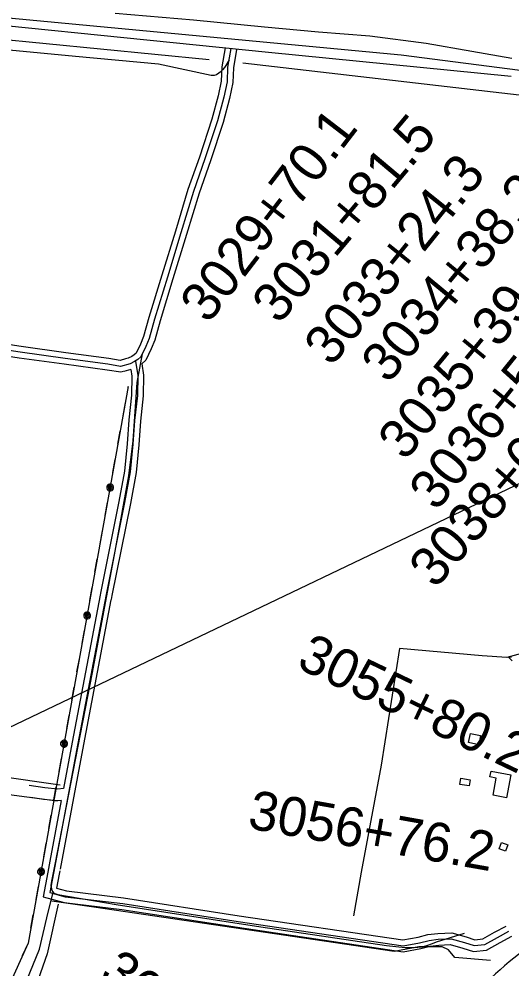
# Model space of a CAD drawing. Extents: x 3279314 to 3317160, y 734079 to 759431.
# Drawn here: x 3294543 to 3295805, y 747608 to 750044 of the extents above; entities that cross this region are included whole.
import ezdxf

# ---------------------------------------------------------------- set-up
doc = ezdxf.new("R2010")
doc.units = 0
for name, color, linetype in [('V-BLDG-OTLN', 7, 'Continuous'), ('V-DTCH-CNTR', 7, 'Continuous'), ('V-LEVE-TOET', 7, 'Continuous'), ('V-ROAD-CNTR', 7, 'Continuous'), ('V-SITE-VEGE', 7, 'Continuous'), ('V-SURV-IDEN', 7, 'Continuous'), ('V-TOPO-SHOR', 7, 'Continuous'), ('V-UTIL-LINE', 7, 'Continuous')]:
    doc.layers.add(name, color=color, linetype=linetype)

msp = doc.modelspace()

# ---------------------------------------------------------------- linework, layer by layer
at = {"layer": 'V-BLDG-OTLN'}
for points in [[(3295696.7, 748187), (3295701.5, 748210.5), (3295727.5, 748205.2), (3295722.7, 748181.6)], [(3295793.6, 748045.2), (3295759.3, 748051.6), (3295767.5, 748095.7), (3295751.4, 748098.7), (3295754.1, 748113.3), (3295804.5, 748103.8)], [(3295698.2, 748075.7), (3295674.1, 748079.4), (3295676.5, 748095.2), (3295700.7, 748091.4)], [(3295797.3, 747924.7), (3295791.1, 747908), (3295774.9, 747914.1), (3295781.1, 747930.8)]]:
    msp.add_lwpolyline(points, close=True, dxfattribs=at)
at = {"layer": 'V-DTCH-CNTR'}
for points in [[(3295082.8, 749939.3), (3295073.8, 749925.1), (3295070.3, 749920.2), (3295065.2, 749913.8), (3295059.4, 749907.7), (3295055.6, 749905.1), (3295050, 749901), (3295044.1, 749899.2), (3295036.5, 749898.9), (3294900.9, 749928.5), (3294688.4, 749948.3), (3294229.8, 749992), (3294186.6, 750004), (3294063.1, 750020.7), (3293953.1, 750030.8), (3293487.8, 750078.8), (3292934.7, 750134), (3292542.1, 750171.5), (3292213, 750206.2)], [(3294859, 749184.8), (3294845.4, 749111.2), (3294835.6, 748961.5), (3294824.2, 748871.4), (3294789.3, 748677.9), (3294731.1, 748367.1), (3294675.3, 748080.7), (3294636.1, 747878.2), (3294626.4, 747831.3), (3294625.1, 747821.3), (3294625.6, 747816.2), (3294627.6, 747807), (3294629.8, 747803.8), (3294633, 747800.8), (3294638.2, 747798.4), (3294643.3, 747797.4), (3294792.7, 747771.7), (3295163.8, 747714.4), (3295485.9, 747666.4), (3295534, 747661.2), (3295557, 747661.1), (3295566.2, 747661.4), (3295578.4, 747662.5), (3295591.6, 747667.2), (3295604.3, 747671.3), (3295614.3, 747675.2), (3295686.4, 747698)], [(3294093.7, 746795.9), (3294100.8, 746817.4), (3294112.1, 746842.3), (3294134, 746884.8), (3294317.1, 747143.4), (3294354.6, 747199.3), (3294407, 747286.1), (3294470, 747391.3), (3294520.1, 747482.2), (3294563.8, 747576.8), (3294595.6, 747657), (3294614.4, 747737.2), (3294630.7, 747802.9)]]:
    msp.add_lwpolyline(points, dxfattribs=at)
at = {"layer": 'V-LEVE-TOET'}
msp.add_lwpolyline([(3294790.3, 750059.1), (3294991.3, 750042.3), (3295173, 750024), (3295311.4, 750011.2), (3295443.4, 750001.5), (3295587.6, 749982.1), (3295705.2, 749961.8), (3295807.8, 749943.5)], dxfattribs=at)
at = {"layer": 'V-ROAD-CNTR'}
for points in [[(3295805.4, 749896.5), (3295183.5, 749958.3), (3294136.9, 750064.8)], [(3295086.7, 749968.2), (3295078.5, 749920.3), (3295077.2, 749882.8), (3295069.1, 749843.4), (3295052.3, 749783.1), (3295020.3, 749685), (3294991, 749601.9), (3294958.8, 749495.5), (3294923.9, 749382), (3294890.8, 749273.6), (3294877.3, 749224.5), (3294868.6, 749203.8), (3294856, 749177.4), (3294848.2, 749170.1), (3294839.6, 749165), (3294828.8, 749159.4), (3294803.9, 749152.7), (3294771.4, 749158), (3294661.7, 749172.8), (3294546.3, 749188.9), (3294432.5, 749206.1)], [(3295086.7, 749968.2), (3295078.5, 749920.3), (3295077.2, 749882.8), (3295069.1, 749843.4), (3295052.3, 749783.1), (3295020.3, 749685), (3294991, 749601.9), (3294958.8, 749495.5), (3294923.9, 749382), (3294890.8, 749273.6), (3294877.3, 749224.5), (3294868.6, 749203.8), (3294856, 749177.4), (3294848.2, 749170.1), (3294839.6, 749165), (3294828.8, 749159.4), (3294803.9, 749152.7), (3294771.4, 749158), (3294661.7, 749172.8), (3294546.3, 749188.9), (3294432.5, 749206.1)], [(3295071.9, 749970.7), (3295063.5, 749921.9), (3295062.3, 749884.6), (3295054.5, 749847), (3295037.9, 749787.5), (3295006.1, 749689.9), (3294976.8, 749606.6), (3294944.5, 749499.9), (3294909.6, 749386.4), (3294876.4, 749277.8), (3294863.1, 749229.4), (3294854.9, 749209.9), (3294843.7, 749186.4), (3294839.1, 749182.1), (3294832.4, 749178.1), (3294823.3, 749173.5), (3294816.8, 749171.7)], [(3295101.5, 749965.7), (3295093.5, 749918.8), (3295092.2, 749881), (3295083.6, 749839.9), (3295066.6, 749778.8), (3295034.5, 749680.2), (3295005.3, 749597.2), (3294973.2, 749491.1), (3294938.2, 749377.6), (3294905.2, 749269.4), (3294891.5, 749219.6), (3294882.2, 749197.6), (3294868.3, 749168.4), (3294858.4, 749159.1)], [(3294816.8, 749171.7), (3294803.2, 749168), (3294773.6, 749172.8), (3294663.7, 749187.7), (3294548.5, 749203.7), (3294434.8, 749221), (3294233.5, 749251.9), (3294092, 749272.3), (3293962.1, 749297.6), (3293582.6, 749354.4), (3293201, 749409)], [(3294811.3, 749139.2), (3294804.7, 749137.4), (3294769.2, 749143.2), (3294659.6, 749158), (3294544.1, 749174), (3294430.3, 749191.3), (3294345.3, 749204.4)], [(3294842, 749166.4), (3294848.1, 749128.8), (3294847, 749078), (3294839.8, 749013.7), (3294835.5, 748952.6), (3294828.9, 748882), (3294814.3, 748803.3), (3294766.8, 748567.3), (3294694, 748185), (3294631.9, 747851.7), (3294622.3, 747802.1), (3294662, 747791.3), (3294809.6, 747773.6), (3295105.6, 747727.8), (3295528.4, 747665.1), (3295570.7, 747672.9), (3295595.2, 747679.2), (3295618.9, 747682.3), (3295651.5, 747683.5), (3295686.3, 747673.6), (3295710.9, 747665.7), (3295738.1, 747668.7), (3295770.6, 747686.8), (3295800.1, 747702.9)], [(3294842, 749166.4), (3294848.1, 749128.8), (3294847, 749078), (3294839.8, 749013.7), (3294835.5, 748952.6), (3294828.9, 748882), (3294814.3, 748803.3), (3294766.8, 748567.3), (3294694, 748185), (3294631.9, 747851.7), (3294622.3, 747802.1), (3294662, 747791.3), (3294809.6, 747773.6), (3295105.6, 747727.8), (3295528.4, 747665.1), (3295570.7, 747672.9), (3295595.2, 747679.2), (3295618.9, 747682.3), (3295651.5, 747683.5), (3295686.3, 747673.6), (3295710.9, 747665.7), (3295738.1, 747668.7), (3295770.6, 747686.8), (3295800.1, 747702.9)], [(3294830.4, 749144.3), (3294833.1, 749127.8), (3294832, 749079), (3294824.8, 749015.1), (3294820.5, 748953.8), (3294814, 748884), (3294799.6, 748806.2), (3294752, 748570.2), (3294751.2, 748565.6)], [(3294858.4, 749159.1), (3294863.1, 749129.9), (3294862, 749077), (3294854.7, 749012.4), (3294850.4, 748951.3), (3294843.8, 748879.9), (3294829, 748800.5), (3294781.5, 748564.4), (3294779.5, 748554.1)], [(3294830.4, 749144.3), (3294812.6, 749139.5)], [(3294751.2, 748565.6), (3294679.3, 748187.8), (3294657.1, 748069)], [(3294779.3, 748553.2), (3294708.8, 748182.3), (3294649.2, 747862.4)], [(3294657.1, 748069.3), (3294642.8, 748067.2), (3294610, 748070.9), (3294569.3, 748076.4)], [(3294651.6, 748038.2), (3294643.3, 748037), (3294606.3, 748041.1), (3294573.6, 748045.6)], [(3294651.5, 748038.6), (3294622.4, 747882.5)], [(3294622.4, 747882.5), (3294617.2, 747854.5), (3294604.9, 747791.3), (3294659.1, 747776.5), (3294807.5, 747758.7), (3295103.4, 747713), (3295528.7, 747649.9), (3295573.9, 747658.3), (3295598.1, 747664.4), (3295620.1, 747667.3), (3295649.7, 747668.4), (3295681.9, 747659.3), (3295709.4, 747650.4), (3295742.8, 747654.2), (3295777.8, 747673.6), (3295807.3, 747689.7)], [(3294648.3, 747857.6), (3294646.7, 747848.9), (3294639.6, 747812.9), (3294664.9, 747806), (3294811.6, 747788.4), (3295107.9, 747742.6), (3295528.1, 747680.3), (3295567.5, 747687.6), (3295592.4, 747693.9), (3295617.6, 747697.3), (3295653.3, 747698.6), (3295690.6, 747688), (3295712.5, 747680.9), (3295733.5, 747683.3), (3295763.4, 747699.9), (3295792.9, 747716)]]:
    msp.add_lwpolyline(points, dxfattribs=at)
msp.add_arc((3296186, 747152.1), 609.4, 120.5143, 143.7651, dxfattribs=at)
at = {"layer": 'V-SITE-VEGE'}
msp.add_lwpolyline([(3295808.6, 748396.8), (3295804.6, 748399.9), (3295799.8, 748405.4), (3295802.5, 748406.7), (3295806.5, 748407.1)], dxfattribs=at)
at = {"layer": 'V-TOPO-SHOR'}
msp.add_line((3294648.8, 748077.6), (3294058.2, 748163.9), dxfattribs=at)
for points in [[(3290701, 750895.7), (3291905, 750350.8), (3292008.8, 750323.1), (3292144.5, 750291.5), (3292288.2, 750271.9), (3292364, 750260.1), (3294007.8, 750096.5), (3295524, 749952.4), (3295855.2, 749909.3), (3295939, 749881.6), (3296002.9, 749841.9), (3296042.9, 749802.1), (3296070.9, 749766.2), (3296094.9, 749746.4), (3296098.9, 749750.4), (3296098.8, 749774.3), (3296090.8, 749790.2)], [(3295030.7, 749939.3), (3294473.1, 749993.9), (3293628.8, 750080.9), (3292675.8, 750178.5), (3292135.8, 750229)], [(3295117.1, 749931.5), (3295863.3, 749845.5), (3295947.1, 749805.8), (3296007.1, 749754.1), (3296043.1, 749710.3), (3296063.2, 749662.5), (3296079.3, 749598.7), (3296083.4, 749515), (3296112.2, 749144.1)], [(3296169.9, 748366.4), (3295878.6, 748413.5), (3295822.8, 748413.4), (3295794.9, 748405.4), (3295731, 748409.2), (3295519.6, 748428.6), (3295472.4, 748129.4), (3295421.2, 747854), (3295401.5, 747742.3)], [(3293611.4, 748182.8), (3294225.9, 748092.5), (3294640.9, 748037.7)], [(3295752.8, 747627.4), (3295661.1, 747635.2), (3295645.1, 747655.1), (3295629.1, 747663), (3295569.2, 747662.9), (3295505.5, 747650.8), (3294735.3, 747764.6), (3294627.6, 747780.3)], [(3294643.5, 747772.4), (3294615.9, 747644.7), (3294580.3, 747544.9), (3294532.7, 747429.1), (3294449.2, 747321.2), (3294206.7, 746953.6), (3294182.8, 746917.7), (3294147.1, 746853.8), (3294127.3, 746801.9), (3295061, 746676.4)]]:
    msp.add_lwpolyline(points, dxfattribs=at)
at = {"layer": 'V-UTIL-LINE'}
for points in [[(3294823.7, 749101.3), (3294567, 747672.2), (3294455.7, 747427.9), (3294078.1, 746817.4), (3294050.9, 746537.1), (3293880.8, 745906.1), (3293685, 745363.8), (3293337.1, 745210.6), (3293161, 744222.1), (3293091.7, 743807.4)], [(3294823.2, 749098.7), (3294823.7, 749101.3)], [(3294810.2, 749025.9), (3294816.2, 749059.3)], [(3288668.1, 745426), (3296052.2, 748960.2), (3296218.4, 748982.8)], [(3294797.1, 748953), (3294803.1, 748986.5)], [(3294784, 748880.2), (3294790, 748913.7)], [(3294777.1, 748841.8), (3294774.5, 748840.6), (3294776.5, 748839.4), (3294778.9, 748840.6), (3294779.1, 748843.6), (3294775.8, 748844.3), (3294771.9, 748841.7), (3294773, 748837.6), (3294777.4, 748835.5), (3294781.3, 748837.9), (3294783, 748842.1), (3294780.6, 748846.3), (3294775.3, 748847.6), (3294768.2, 748843.4), (3294768.3, 748839.9), (3294769.7, 748836.7), (3294772.2, 748834.2), (3294775.5, 748833), (3294779, 748833), (3294782.2, 748834.4), (3294784.7, 748837), (3294786, 748840.2), (3294785.9, 748843.7), (3294784.5, 748847), (3294782, 748849.4), (3294778.7, 748850.7), (3294775.2, 748850.6), (3294772, 748849.2), (3294769.5, 748846.7), (3294768.2, 748843.4)], [(3294764.2, 748770), (3294770.2, 748803.4)], [(3294751.1, 748697.1), (3294757.1, 748730.6)], [(3294738, 748624.3), (3294744, 748657.8)], [(3294724.9, 748551.5), (3294730.9, 748584.9)], [(3294718, 748513.1), (3294715.4, 748511.9), (3294717.4, 748510.7), (3294719.9, 748511.9), (3294720.1, 748514.8), (3294716.8, 748515.6), (3294712.9, 748513), (3294713.9, 748508.9), (3294718.3, 748506.8), (3294722.2, 748509.2), (3294723.9, 748513.3), (3294721.6, 748517.5), (3294716.2, 748518.8), (3294709.2, 748514.7), (3294709.2, 748511.2), (3294710.6, 748507.9), (3294713.2, 748505.5), (3294716.4, 748504.2), (3294720, 748504.3), (3294723.2, 748505.7), (3294725.6, 748508.2), (3294726.9, 748511.5), (3294726.8, 748515), (3294725.4, 748518.2), (3294722.9, 748520.7), (3294719.6, 748521.9), (3294716.1, 748521.9), (3294712.9, 748520.5), (3294710.5, 748517.9), (3294709.2, 748514.7)], [(3294705.1, 748441.2), (3294711.1, 748474.7)], [(3294692, 748368.4), (3294698.1, 748401.9)], [(3294679, 748295.6), (3294685, 748329)], [(3294665.9, 748222.7), (3294671.9, 748256.2)], [(3294659, 748184.3), (3294656.4, 748183.2), (3294658.4, 748182), (3294660.8, 748183.2), (3294661, 748186.1), (3294657.7, 748186.9), (3294653.8, 748184.3), (3294654.9, 748180.1), (3294659.2, 748178), (3294663.1, 748180.5), (3294664.9, 748184.6), (3294662.5, 748188.8), (3294657.1, 748190.1), (3294650.1, 748185.9), (3294650.2, 748182.4), (3294651.6, 748179.2), (3294654.1, 748176.8), (3294657.4, 748175.5), (3294660.9, 748175.6), (3294664.1, 748177), (3294666.6, 748179.5), (3294667.8, 748182.8), (3294667.8, 748186.3), (3294666.4, 748189.5), (3294663.8, 748191.9), (3294660.6, 748193.2), (3294657.1, 748193.1), (3294653.8, 748191.7), (3294651.4, 748189.2), (3294650.1, 748185.9)], [(3294646.1, 748112.5), (3294652.1, 748146)], [(3294633, 748039.7), (3294639, 748073.1)], [(3294619.9, 747966.8), (3294625.9, 748000.3)], [(3294606.8, 747894), (3294612.8, 747927.5)], [(3294599.9, 747855.6), (3294597.3, 747854.4), (3294599.3, 747853.2), (3294601.8, 747854.4), (3294602, 747857.4), (3294598.7, 747858.1), (3294594.7, 747855.5), (3294595.8, 747851.4), (3294600.2, 747849.3), (3294604.1, 747851.7), (3294605.8, 747855.9), (3294603.4, 747860.1), (3294598.1, 747861.3), (3294591.1, 747857.2), (3294591.1, 747853.7), (3294592.5, 747850.5), (3294595.1, 747848), (3294598.3, 747846.8), (3294601.8, 747846.8), (3294605.1, 747848.2), (3294607.5, 747850.8), (3294608.8, 747854), (3294608.7, 747857.5), (3294607.3, 747860.8), (3294604.8, 747863.2), (3294601.5, 747864.5), (3294598, 747864.4), (3294594.8, 747863), (3294592.3, 747860.5), (3294591.1, 747857.2)], [(3294587, 747783.8), (3294593, 747817.2)], [(3294573.9, 747710.9), (3294579.9, 747744.4)], [(3294552.6, 747640.7), (3294566.7, 747671.6)]]:
    msp.add_lwpolyline(points, dxfattribs=at)

# ---------------------------------------------------------------- texts
at = {"layer": 'V-SURV-IDEN'}
for s, rotation, p in [('3029+70.1', 52.5188, (3295028.8, 749259.4)), ('3031+81.5', 49.93, (3295209.9, 749258)), ('3033+24.3', 51.1742, (3295345.1, 749149.7)), ('3034+38.2', 50.3027, (3295490.5, 749105.5)), ('3035+39.3', 50.4471, (3295533.8, 748907.5)), ('3036+54.0', 51.0864, (3295614.4, 748778.2)), ('3038+04.8', 49.2235, (3295611.7, 748579.5)), ('3055+80.2', 334.3465, (3295251.9, 748381)), ('3056+76.2', 349.9446, (3295127, 747967.5)), ('3068+39.8', 321.9734, (3294744.6, 747583.9))]:
    msp.add_text(s, height=100, rotation=rotation, dxfattribs=at).set_placement(p)

doc.saveas('drawing.dxf')
